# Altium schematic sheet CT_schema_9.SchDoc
size 274 x 160 mm
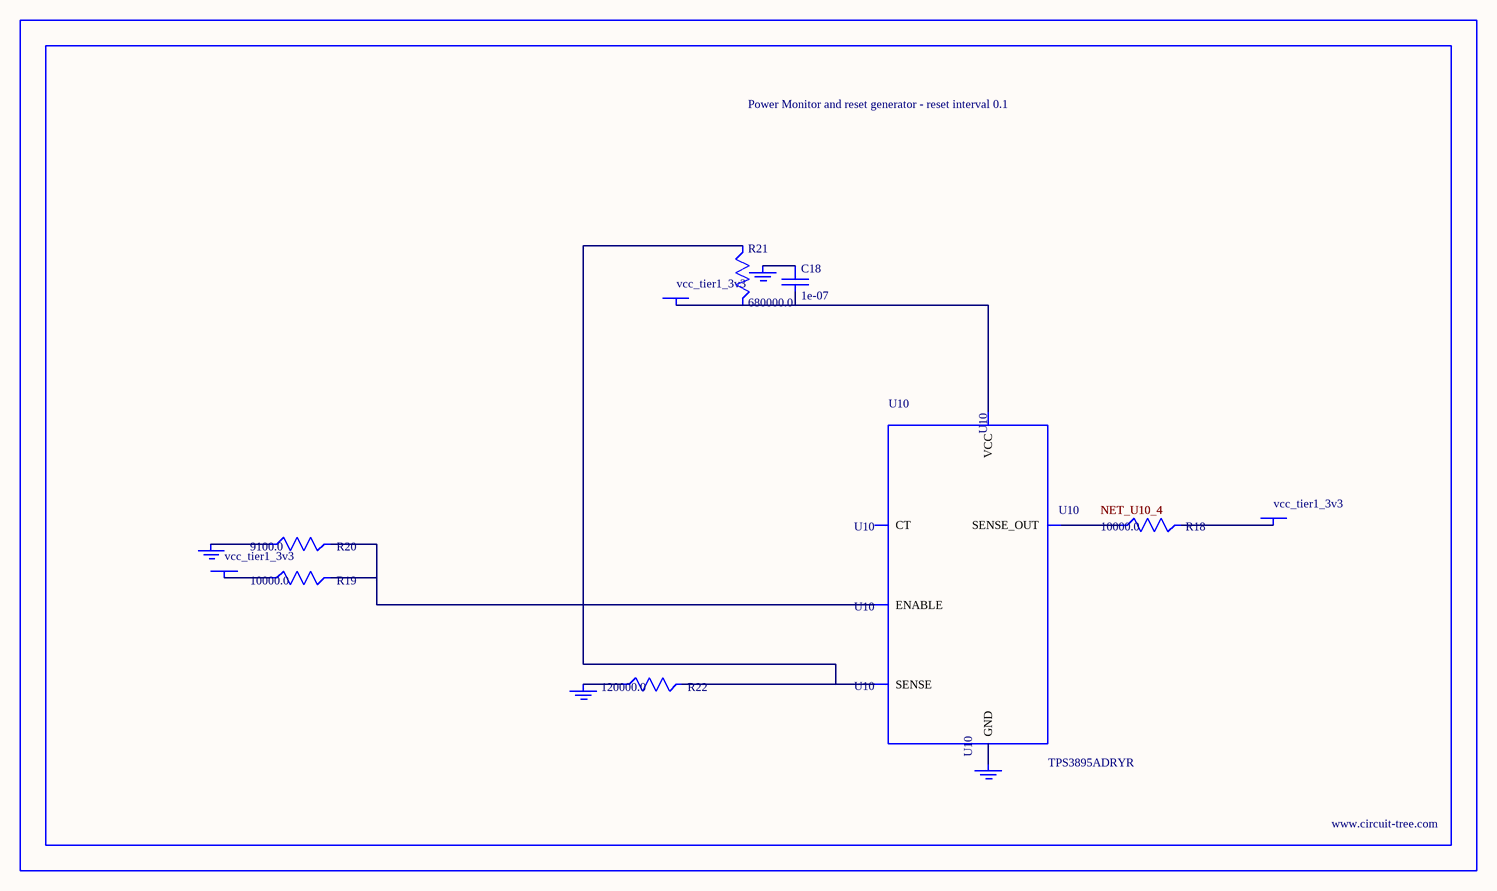
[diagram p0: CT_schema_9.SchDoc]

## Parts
BORDER8  (no value)
C18  1e-07  [C0402]
GND_INSTANCE_8_0  (no value)
GND_INSTANCE_8_1  (no value)
GND_INSTANCE_8_2  (no value)
GND_INSTANCE_8_3  (no value)
POWER_INSTANCE_8_0  vcc_tier1_3v3
POWER_INSTANCE_8_1  vcc_tier1_3v3
POWER_INSTANCE_8_2  vcc_tier1_3v3
R18  10000.0  [R0603]
R19  10000.0  [R0603]
R20  9100.0  [R0603]
R21  680000.0  [R0603]
R22  120000.0  [R0603]
U10  TPS3895ADRYR  [SON-6]

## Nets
NetC18_1: C18.1 GND_INSTANCE_8_2.0(GND)
NetC18_2: C18.2 POWER_INSTANCE_8_2.0(PWR) R21.2 U10.6(VCC)
NetGND_INSTANCE_8_0_0: GND_INSTANCE_8_0.0(GND) R20.1
NetGND_INSTANCE_8_1_0: GND_INSTANCE_8_1.0(GND) R22.1
NetGND_INSTANCE_8_3_0: GND_INSTANCE_8_3.0(GND) U10.2(GND)
NetPOWER_INSTANCE_8_0_0: POWER_INSTANCE_8_0.0(PWR) R19.1
NetPOWER_INSTANCE_8_1_0: POWER_INSTANCE_8_1.0(PWR) R18.2
NetR18_1: R18.1 U10.4(SENSE_OUT)
NetR19_2: R19.2 R20.2 U10.1(ENABLE)
NetR21_1: R21.1 R22.2 U10.3(SENSE)

Not connected (* = marked no-connect by the designer): U10 5(CT)

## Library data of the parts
BORDER8 = BORDER_PAGE8
C18 = C0402C104K3RACTU
GND_INSTANCE_8_0-GND_INSTANCE_8_3 = GND
POWER_INSTANCE_8_0-POWER_INSTANCE_8_2 = PWR
R18 R19 = RC0603JR-0710KL
R20 = RC0603JR-079K1L
R21 = RC0603JR-07680KL
R22 = RC0603JR-07120KL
